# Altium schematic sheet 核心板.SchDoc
size A4; PageSetup: Record=PageOptions|CenterHorizontal=True|CenterVertical=True|PrintScale=1.00|XCorrection=1.00|YCorrection=1.00|PrintKind=2|BorderSize=5000000|LeftOffset=0|BottomOffset=0|Orientation=2|PaperLength=1000|PaperWidth=1000|Scale=100|PaperSource=7|PrintQuality=-4|MediaType=1|DitherType=10|PaperKind=A4|PrintScaleMode=1
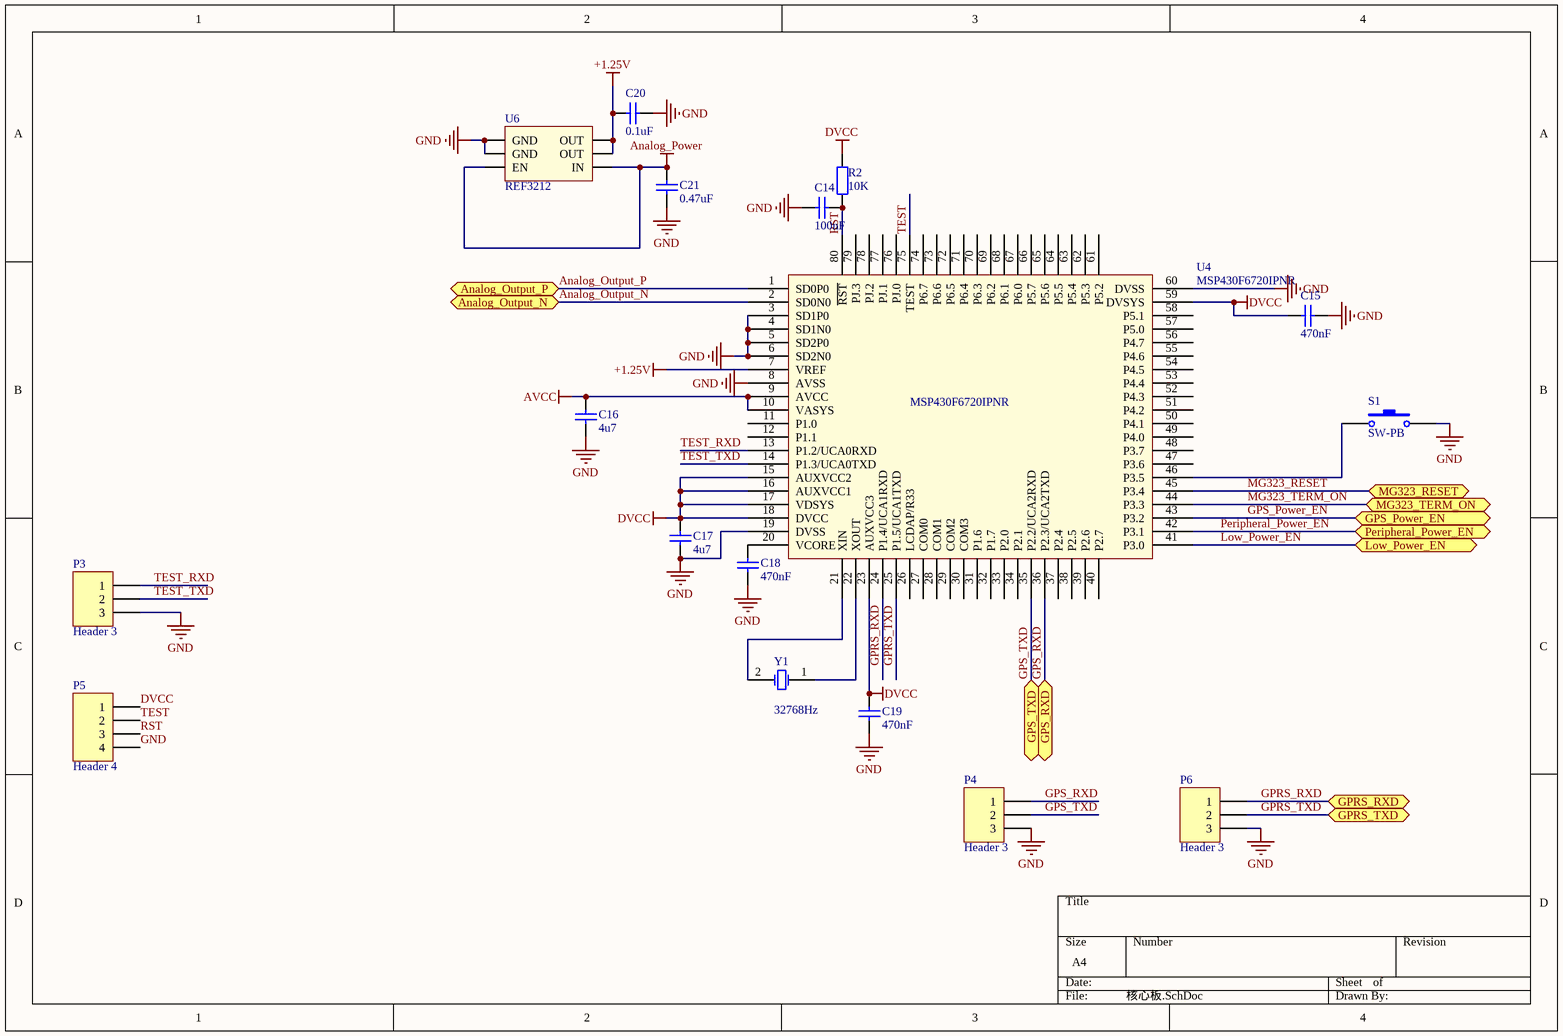
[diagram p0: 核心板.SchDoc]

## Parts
C14  value 100nF  [0805C]
C15  value 470nF  [0805C]
C16  value 4u7  [0805C]
C17  value 4u7  [0805C]
C18  value 470nF  [0805C]
C19  value 470nF  [0805C]
C20  value 0.1uF  [0805C]
C21  value 0.47uF  [0805C]
P3  Header 3  [HDR1X3]
P4  Header 3  [HDR1X3]
P5  Header 4  [HDR1X4]
P6  Header 3  [HDR1X3]
R2  value 10K  [0805R]
S1  SW-PB  [SW-KEY]
U4  MSP430F6720IPNR  [QFP-80]
U6  REF3212  [SOT23-6]
Y1  value 32768Hz  [XTAL2]  (hidden comment: XTAL)

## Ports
Analog_Output_N, Analog_Output_P, GPRS_RXD, GPRS_TXD, GPS_Power_EN, GPS_RXD, GPS_TXD, Low_Power_EN, MG323_RESET, MG323_TERM_ON, Peripheral_Power_EN

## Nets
+1.25V: C20.2 U4.7(VREF) U6.5(OUT) U6.6(OUT)
Analog_Power: C21.2 U6.3(EN) U6.4(IN)
AVCC: C16.1 U4.9(AVCC) U4.10(VASYS)
DVCC: C15.1 C17.1 C19.1 P5.1 R2.1 U4.15(AUXVCC2) U4.16(AUXVCC1) U4.17(VDSYS) U4.18(DVCC) U4.23(AUXVCC3) U4.59(DVSYS)
GND: C14.1 C15.2 C16.2 C17.2 C18.2 C19.2 C20.1 C21.1 P3.3 P4.3 P5.4 P6.3 S1.2 U4.3(SD1P0) U4.4(SD1N0) U4.5(SD2P0) U4.6(SD2N0) U4.8(AVSS) U4.19(DVSS) U4.60(DVSS) U6.1(GND) U6.2(GND)
Analog_Output_N: U4.2(SD0N0) ; port Analog_Output_N
Analog_Output_P: U4.1(SD0P0) ; port Analog_Output_P
GPRS_RXD: P6.1 U4.24(P1.4/UCA1RXD) ; port GPRS_RXD
GPRS_TXD: P6.2 U4.25(P1.5/UCA1TXD) ; port GPRS_TXD
GPS_Power_EN: U4.43(P3.2) ; port GPS_Power_EN
GPS_RXD: P4.1 U4.36(P2.3/UCA2TXD) ; port GPS_RXD
GPS_TXD: P4.2 U4.35(P2.2/UCA2RXD) ; port GPS_TXD
Low_Power_EN: U4.41(P3.0) ; port Low_Power_EN
MG323_RESET: U4.45(P3.4) ; port MG323_RESET
MG323_TERM_ON: U4.44(P3.3) ; port MG323_TERM_ON
Peripheral_Power_EN: U4.42(P3.1) ; port Peripheral_Power_EN
RST: C14.2 P5.3 R2.2 U4.80(~{RST})
TEST: P5.2 U4.75(TEST)
TEST_RXD: P3.1 U4.13(P1.2/UCA0RXD)
TEST_TXD: P3.2 U4.14(P1.3/UCA0TXD)
NetC18_1: C18.1 U4.20(VCORE)
NetS1_1: S1.1 U4.46(P3.5)
NetU4_21: U4.21(XIN) Y1.2(OSC2)
NetU4_22: U4.22(XOUT) Y1.1(OSC1)

Not connected (* = marked no-connect by the designer): U4 11(P1.0) 12(P1.1) 26(LCDAP/R33) 27(COM0) 28(COM1) 29(COM2) 30(COM3) 31(P1.6) 32(P1.7) 33(P2.0) 34(P2.1) 37(P2.4) 38(P2.5) 39(P2.6) 40(P2.7) 47(P3.6) 48(P3.7) 49(P4.0) 50(P4.1) 51(P4.2) 52(P4.3) 53(P4.4) 54(P4.5) 55(P4.6) 56(P4.7) 57(P5.0) 58(P5.1) 61(P5.2) 62(P5.3) 63(P5.4) 64(P5.5) 65(P5.6) 66(P5.7) 67(P6.0) 68(P6.1) 69(P6.2) 70(P6.3) 71(P6.4) 72(P6.5) 73(P6.6) 74(P6.7) 76(PJ.0) 77(PJ.1) 78(PJ.2) 79(PJ.3)

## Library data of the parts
C14-C19 = Cap: 贴片电容
C20 C21 = Cap: 瓷片电容
P3 P4 P6 = Header 3: Header, 3-Pin
P5 = Header 4: Header, 4-Pin
R2 = Res2: 贴片电阻
S1 = SW-PB: Switch
U4 = MSP430F6720: MSP430处理器80引脚封装
U6 = REF3212: 串联基准
Y1 = XTAL: 无源晶振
